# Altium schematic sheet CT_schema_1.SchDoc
size 495 x 480 mm
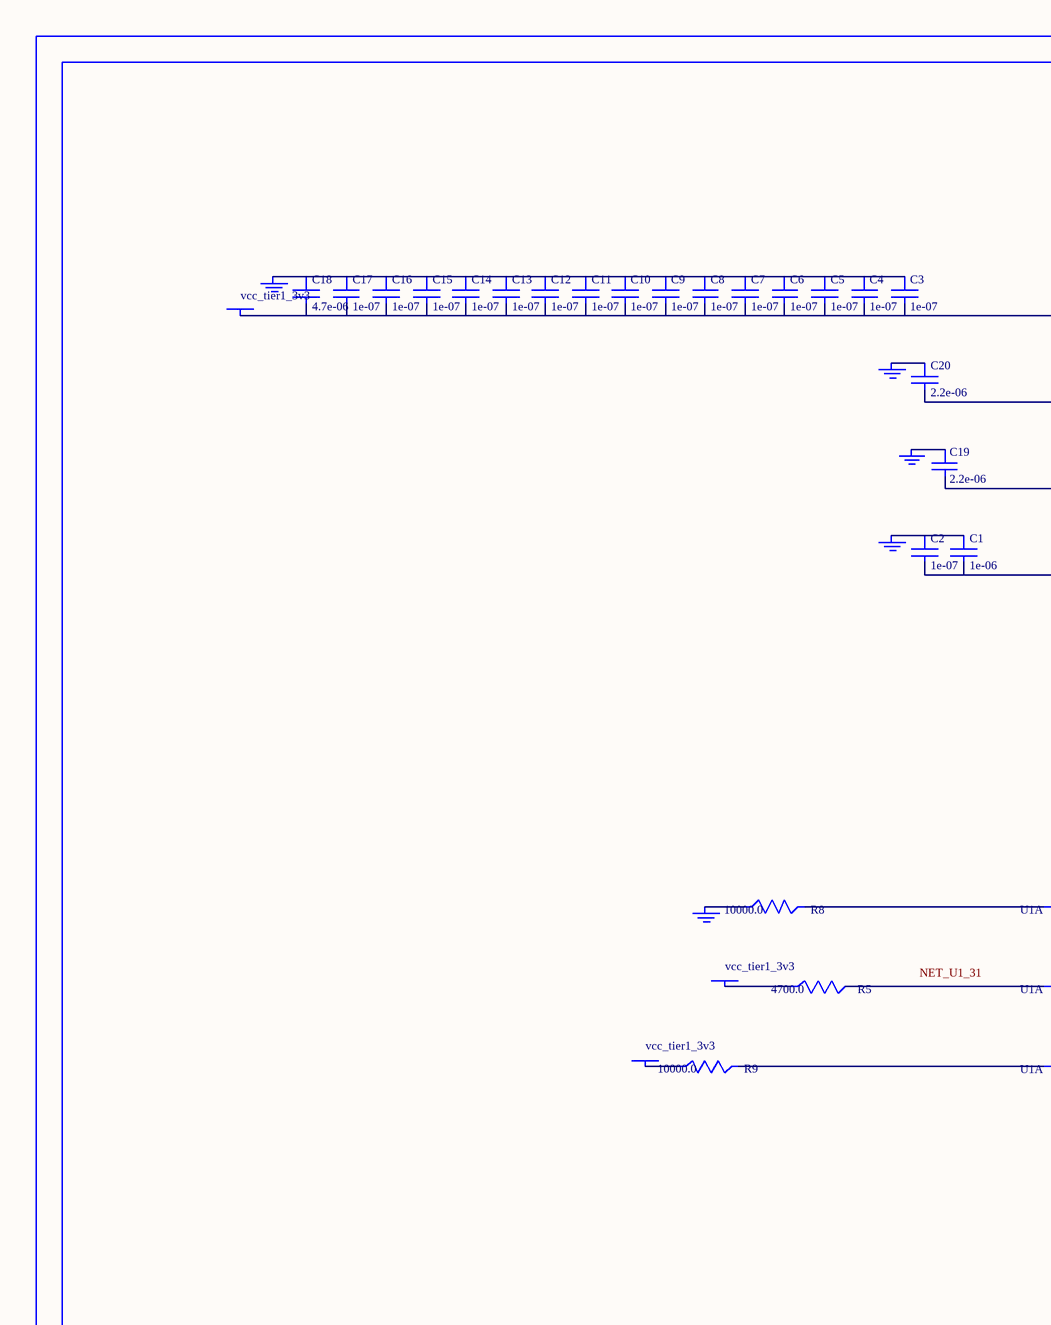
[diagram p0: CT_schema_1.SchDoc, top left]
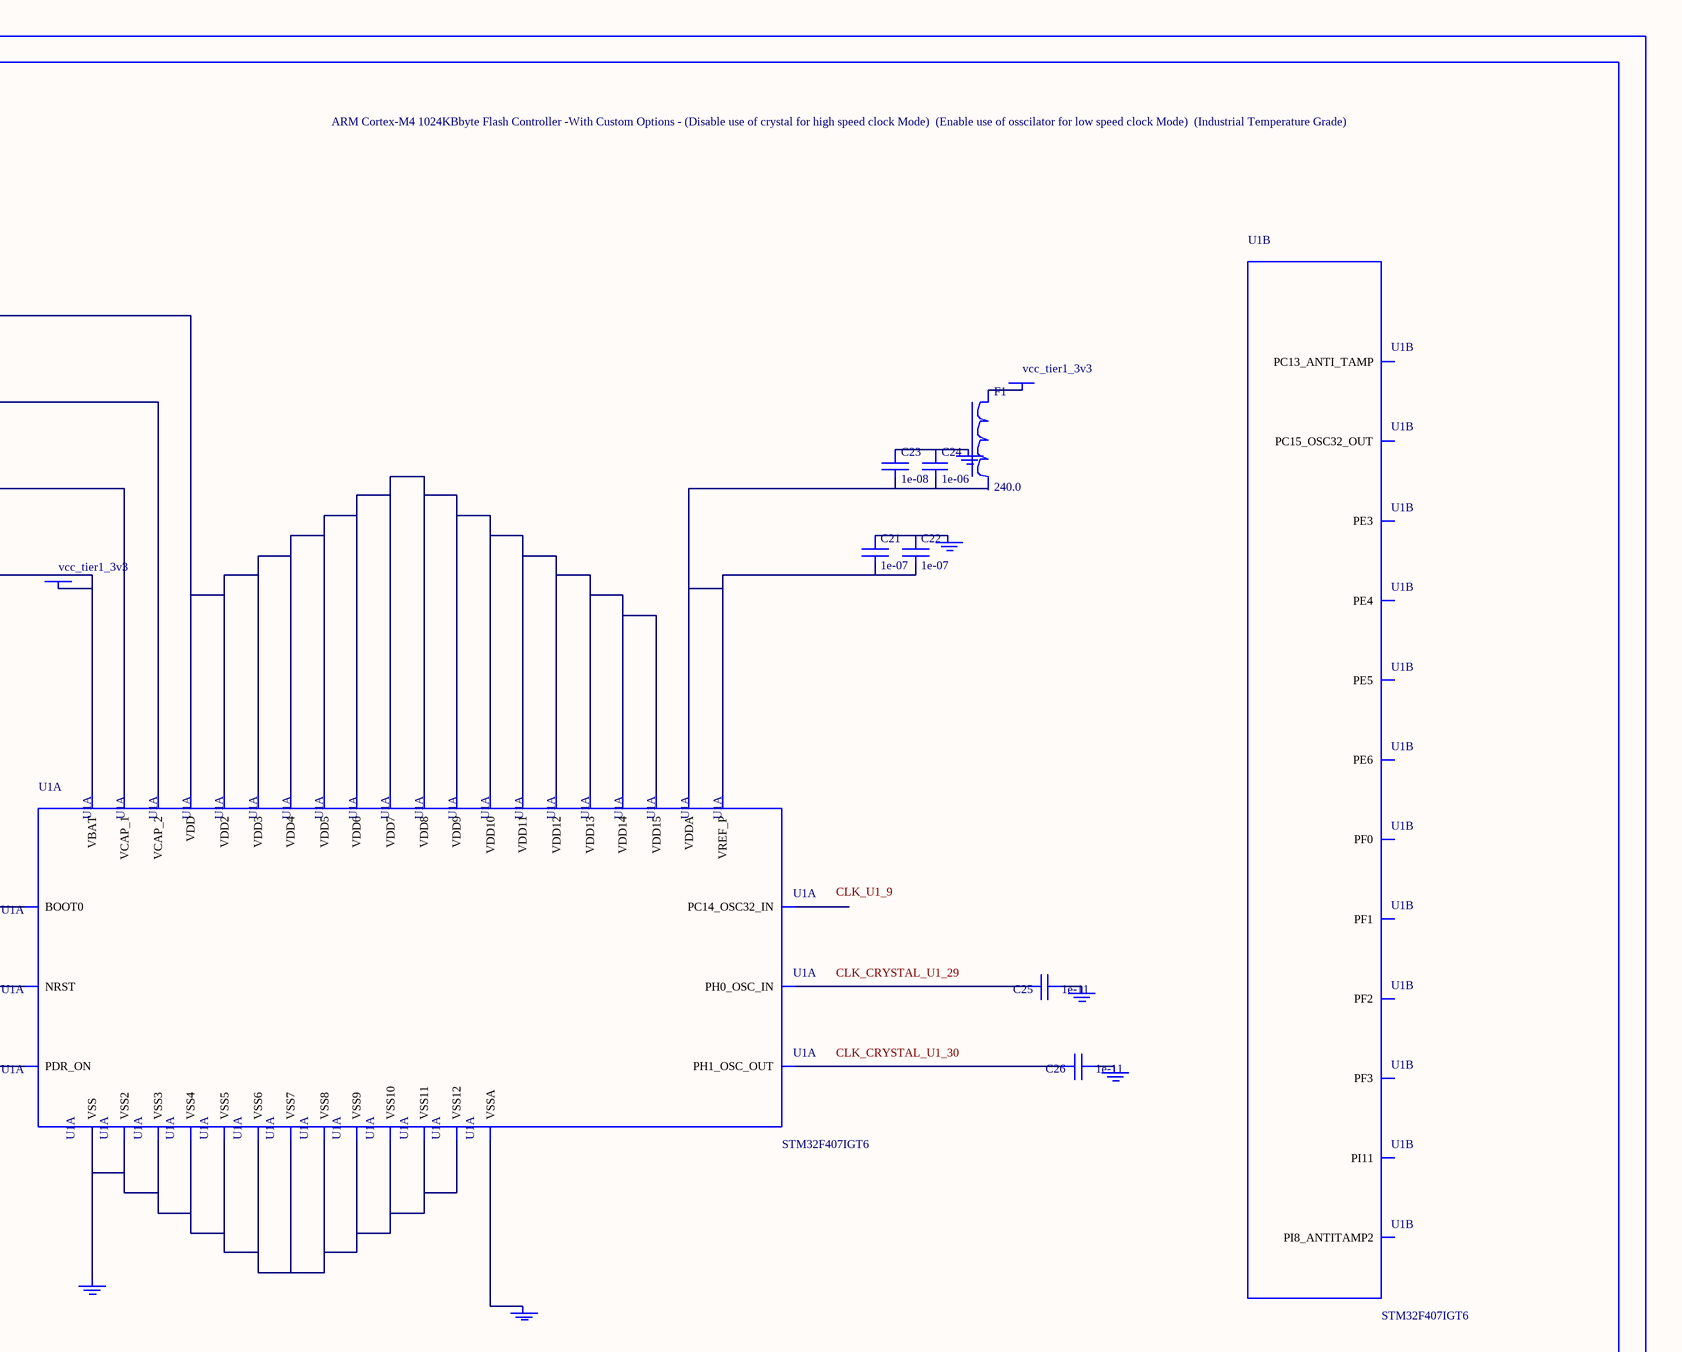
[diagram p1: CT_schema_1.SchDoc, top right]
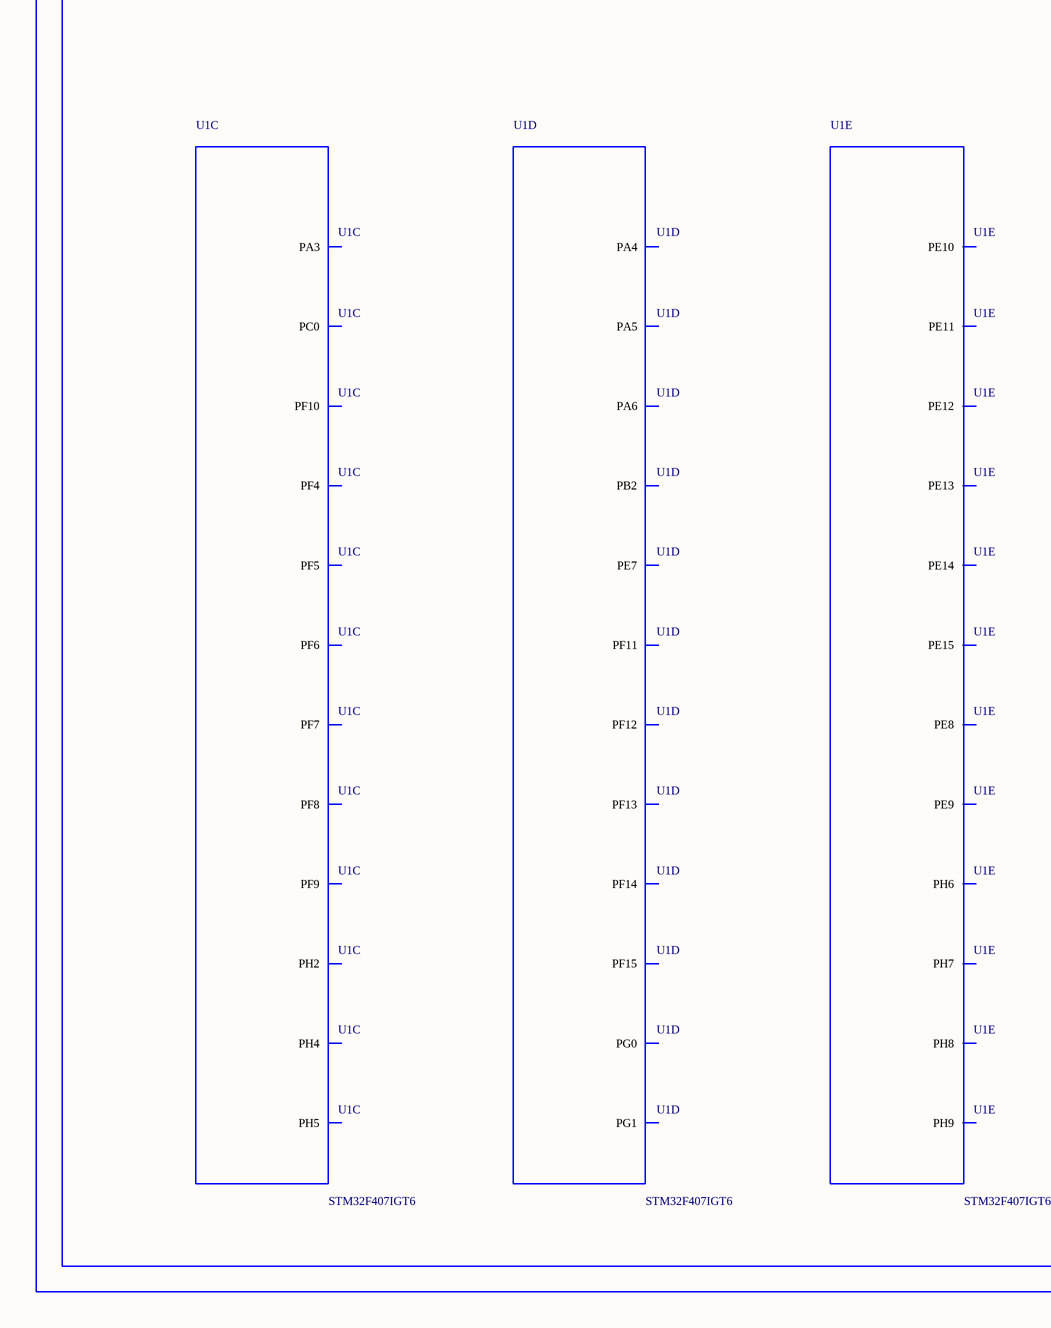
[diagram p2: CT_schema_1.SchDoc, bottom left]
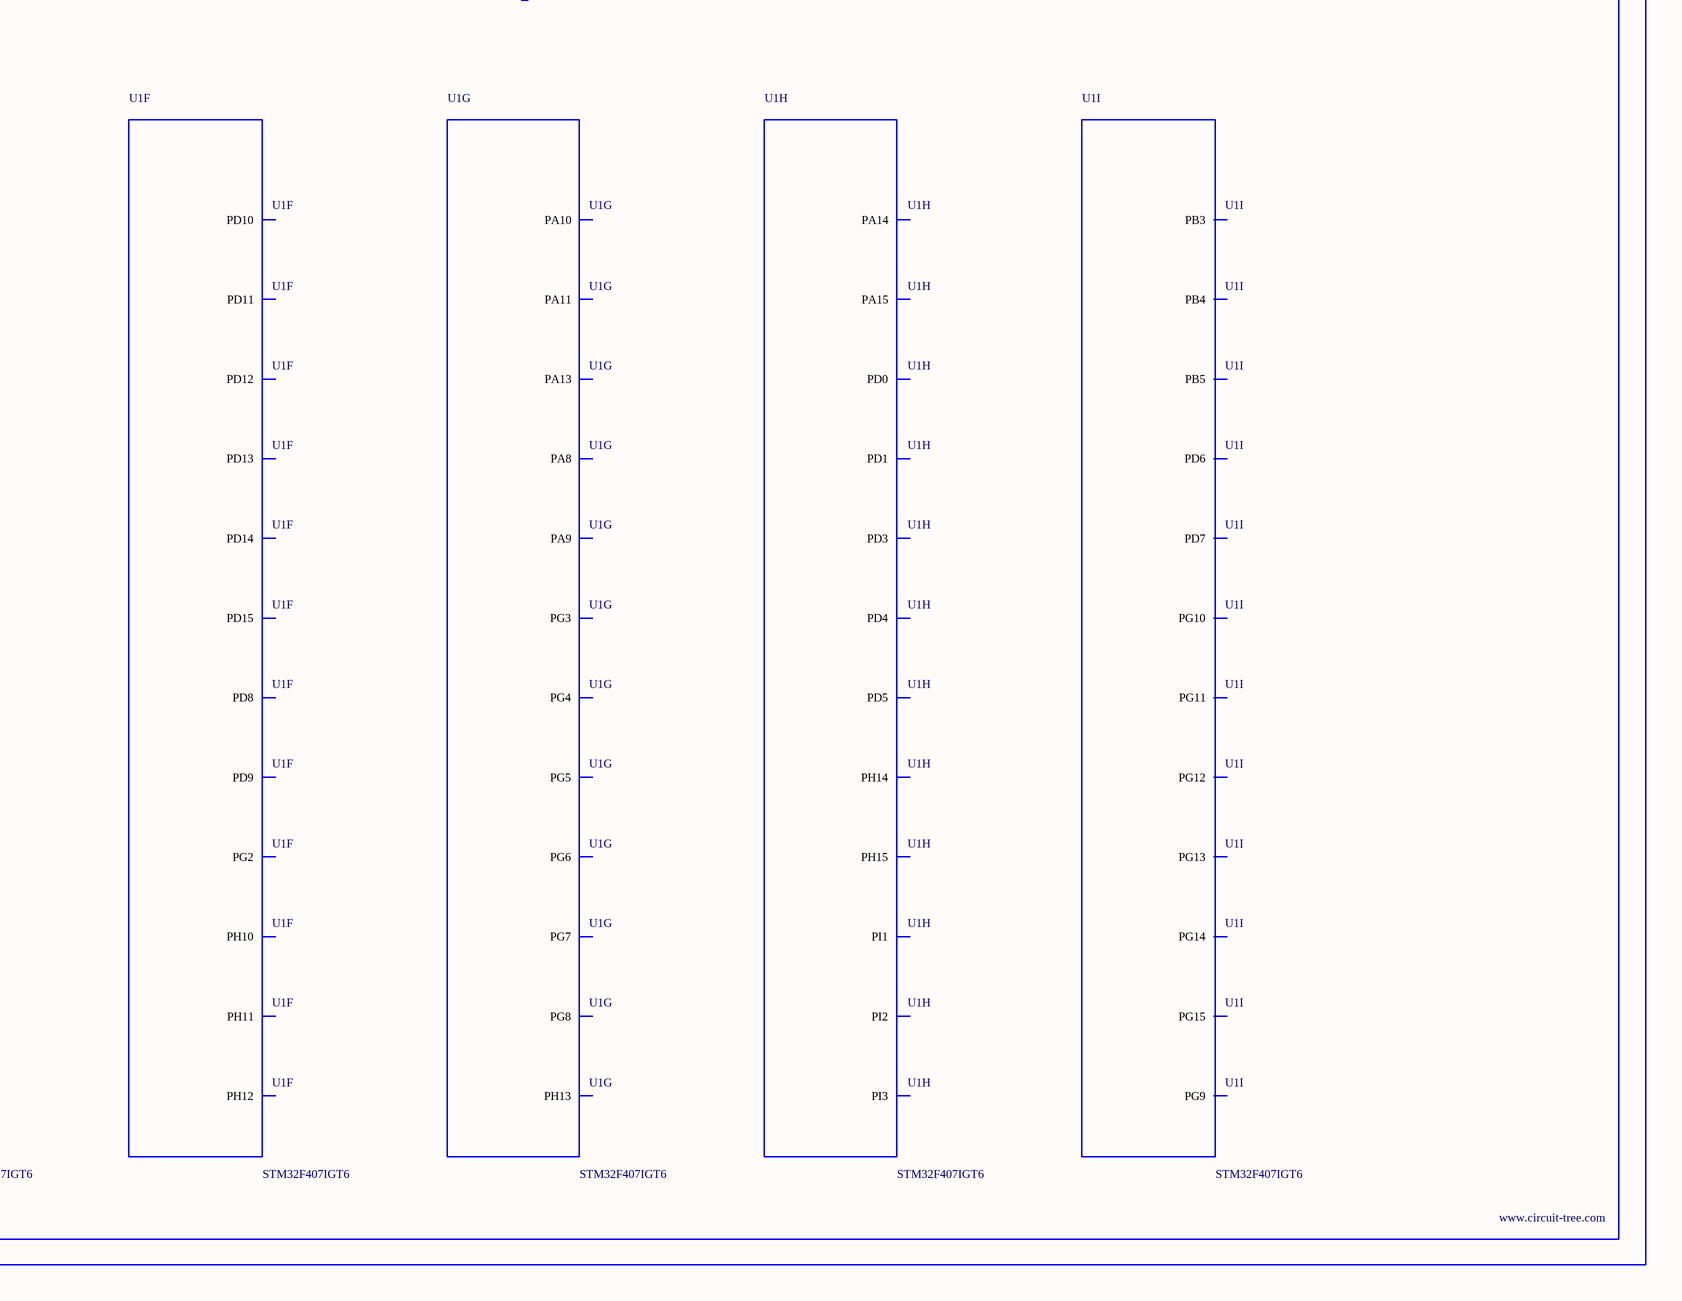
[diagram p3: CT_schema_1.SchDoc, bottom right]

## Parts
BORDER0  (no value)
C1  1e-06  [C0603]
C2  1e-07  [C0603]
C3  1e-07  [C0603]
C4  1e-07  [C0603]
C5  1e-07  [C0603]
C6  1e-07  [C0603]
C7  1e-07  [C0603]
C8  1e-07  [C0603]
C9  1e-07  [C0603]
C10  1e-07  [C0603]
C11  1e-07  [C0603]
C12  1e-07  [C0603]
C13  1e-07  [C0603]
C14  1e-07  [C0603]
C15  1e-07  [C0603]
C16  1e-07  [C0603]
C17  1e-07  [C0603]
C18  4.7e-06  [C0603]
C19  2.2e-06  [C0603]
C20  2.2e-06  [C0603]
C21  1e-07  [C0603]
C22  1e-07  [C0603]
C23  1e-08  [C0603]
C24  1e-06  [C0603]
C25  1e-11  [C0402]
C26  1e-11  [C0402]
F1  240.0  [L0603]
GND_INSTANCE_0_0  (no value)
GND_INSTANCE_0_1  (no value)
GND_INSTANCE_0_2  (no value)
GND_INSTANCE_0_3  (no value)
GND_INSTANCE_0_4  (no value)
GND_INSTANCE_0_5  (no value)
GND_INSTANCE_0_6  (no value)
GND_INSTANCE_0_7  (no value)
GND_INSTANCE_0_8  (no value)
GND_INSTANCE_0_9  (no value)
GND_INSTANCE_0_10  (no value)
POWER_INSTANCE_0_0  vcc_tier1_3v3
POWER_INSTANCE_0_1  vcc_tier1_3v3
POWER_INSTANCE_0_2  vcc_tier1_3v3
POWER_INSTANCE_0_3  vcc_tier1_3v3
POWER_INSTANCE_0_4  vcc_tier1_3v3
R5  4700.0  [R0603]
R8  10000.0  [R0603]
R9  10000.0  [R0603]
U1  STM32F407IGT6  [LQFP176]  (parts A,B,C,D,E,F,G,H,I of 14)

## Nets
NetC1_1: C1.1 C2.1 GND_INSTANCE_0_0.0(GND)
NetC1_2: C1.2 C2.2 POWER_INSTANCE_0_0.0(PWR) U1.6(VBAT)
NetC3_1: C3.1 C4.1 C5.1 C6.1 C7.1 C8.1 C9.1 C10.1 C11.1 C12.1 C13.1 C14.1 C15.1 C16.1 C17.1 C18.1 GND_INSTANCE_0_1.0(GND)
NetC3_2: C3.2 C4.2 C5.2 C6.2 C7.2 C8.2 C9.2 C10.2 C11.2 C12.2 C13.2 C14.2 C15.2 C16.2 C17.2 C18.2 POWER_INSTANCE_0_1.0(PWR) U1.15(VDD) U1.23(VDD2) U1.36(VDD3) U1.49(VDD4) U1.62(VDD5) U1.72(VDD6) U1.82(VDD7) U1.91(VDD8) U1.103(VDD9) U1.114(VDD10) U1.127(VDD11) U1.136(VDD12) U1.149(VDD13) U1.159(VDD14) U1.172(VDD15)
NetC19_1: C19.1 GND_INSTANCE_0_7.0(GND)
NetC19_2: C19.2 U1.81(VCAP_1)
NetC20_1: C20.1 GND_INSTANCE_0_8.0(GND)
NetC20_2: C20.2 U1.125(VCAP_2)
NetC21_1: C21.1 C22.1 GND_INSTANCE_0_5.0(GND)
NetC21_2: C21.2 C22.2 C23.2 C24.2 U1.38(VREF_P) U1.39(VDDA)
NetC23_1: C23.1 C24.1 GND_INSTANCE_0_6.0(GND)
NetC25_1: C25.1 GND_INSTANCE_0_2.0(GND)
NetC25_2: C25.2 U1.29(PH0_OSC_IN)
NetC26_1: C26.1 GND_INSTANCE_0_3.0(GND)
NetC26_2: C26.2 U1.30(PH1_OSC_OUT)
NetF1_1: F1.1 POWER_INSTANCE_0_2.0(PWR)
NetGND_INSTANCE_0_4_0: GND_INSTANCE_0_4.0(GND) U1.37(VSSA)
NetGND_INSTANCE_0_9_0: GND_INSTANCE_0_9.0(GND) R8.1
NetGND_INSTANCE_0_10_0: GND_INSTANCE_0_10.0(GND) U1.14(VSS) U1.22(VSS2) U1.48(VSS3) U1.61(VSS4) U1.71(VSS5) U1.90(VSS6) U1.102(VSS7) U1.113(VSS8) U1.126(VSS9) U1.135(VSS10) U1.148(VSS11) U1.158(VSS12)
NetPOWER_INSTANCE_0_3_0: POWER_INSTANCE_0_3.0(PWR) R9.1
NetPOWER_INSTANCE_0_4_0: POWER_INSTANCE_0_4.0(PWR) R5.1
NetR5_2: R5.2 U1.31(NRST)
NetR8_2: R8.2 U1.166(BOOT0)
NetR9_2: R9.2 U1.171(PDR_ON)

Not connected (* = marked no-connect by the designer): F1 2; U1 2(PE3) 3(PE4) 4(PE5) 5(PE6) 7(PI8_ANTITAMP2) 8(PC13_ANTI_TAMP) 9(PC14_OSC32_IN) 10(PC15_OSC32_OUT) 13(PI11) 16(PF0) 17(PF1) 18(PF2) 19(PF3) 20(PF4) 21(PF5) 24(PF6) 25(PF7) 26(PF8) 27(PF9) 28(PF10) 32(PC0) 43(PH2) 45(PH4) 46(PH5) 47(PA3) 50(PA4) 51(PA5) 52(PA6) 58(PB2) 59(PF11) 60(PF12) 63(PF13) 64(PF14) 65(PF15) 66(PG0) 67(PG1) 68(PE7) 69(PE8) 70(PE9) 73(PE10) 74(PE11) 75(PE12) 76(PE13) 77(PE14) 78(PE15) 83(PH6) 84(PH7) 85(PH8) 86(PH9) 87(PH10) 88(PH11) 89(PH12) 96(PD8) 97(PD9) 98(PD10) 99(PD11) 100(PD12) 101(PD13) 104(PD14) 105(PD15) 106(PG2) 107(PG3) 108(PG4) 109(PG5) 110(PG6) 111(PG7) 112(PG8) 119(PA8) 120(PA9) 121(PA10) 122(PA11) 124(PA13) 128(PH13) 129(PH14) 130(PH15) 132(PI1) 133(PI2) 134(PI3) 137(PA14) 138(PA15) 142(PD0) 143(PD1) 145(PD3) 146(PD4) 147(PD5) 150(PD6) 151(PD7) 152(PG9) 153(PG10) 154(PG11) 155(PG12) 156(PG13) 157(PG14) 160(PG15) 161(PB3) 162(PB4) 163(PB5)

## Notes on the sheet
- Labels drawn without touching a wire or pin: CLK_CRYSTAL_U1_29, CLK_CRYSTAL_U1_30, CLK_U1_9, NET_U1_31

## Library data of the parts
BORDER0 = BORDER_PAGE0
C1 C24 = C0603C105K3RACTU
C2-C17 C21 C22 = 06035C104K4Z2A
C18 = GRM188R6YA475KE15D
C19 C20 = C0603C225K8RACTU
C23 = 06035C103K4Z2A
C25 C26 = C0402C100K3GACTU
F1 = Z0603C241ASMST
GND_INSTANCE_0_0-GND_INSTANCE_0_10 = GND
POWER_INSTANCE_0_0-POWER_INSTANCE_0_4 = PWR
R5 = RC0603JR-074K7L
R8 R9 = RC0603JR-0710KL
